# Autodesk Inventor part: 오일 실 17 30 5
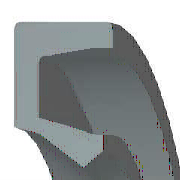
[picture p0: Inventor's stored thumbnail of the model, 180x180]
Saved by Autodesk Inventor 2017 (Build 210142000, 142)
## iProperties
IsCustomPart: 1
Created: 2012-02
Part Number: 오일 실 17 30 5
Material: 고무
Description: 오일 실 - 비스프링, 금속 케이스 GM
Document SubType Name: Modeling
Standard: JIS B 2402
Designer: mduedu
Standards Organization: JIS
Language: ko-KR
Size Designation: 17 30 5 C
Categories: <MemberInstance><Categories><Category DisplayName="샤프트 부품" InternalName="7f7aeb1f-a693-4053-b835-cee3144e0d98" Mnemonic="SHFT"><Category DisplayName="실링" Intern
Density: 0.93 g/cm^3
Appearance: 검은색
Mass: 0.920963 g
Surface Area: 18.5193 cm^2
Volume: 0.990282 cm^3
Author: mduedu
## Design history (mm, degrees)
fillet "모깎기2" dims "d36" = 0.5
body "Solid1"
revolve "회전1" stored, may be unused: angle "d27" = 360 deg
fillet "모깎기1" dims "d28" = 0.25 (= 0.05 x b)
chamfer "모따기1" distance "d29" = 0.07143 (= 0.0142857 x b); stored, may be unused: second distance "d30" = 0.25 (= 0.05 x b), angle "d35" = 45 deg
sketch "스케치2"
  geometry: L1 (-9.367, -3.238)-(-10.233, -3.863); L2 (-8.5, -1.625)-(-9.367, -3.238); L3 (-9.15, -1)-(-8.5, -1.625); L4 (-11.317, -3.75)-(-9.15, -1); L5 (-13.075, -3.75)-(-11.317, -3.75); L6 (-14.375, -1.25)-(-13.075, -3.75); L7 (-14.375, 0)-(-14.375, -1.25); L8 (-15, 0)-(-14.375, 0); L9 (-15, -5)-(-15, 0); L10 (-11.129, -5)-(-15, -5); L11 (-10.233, -3.863)-(-11.129, -5); L12 (0, -9.6)-(0, 1.6) reference; L13 (-14, 0)-(-28, 0) reference
  constraints: 22 end point, 3 horizontal, 2 vertical, 1 parallel
  dimensions: "d2" = 5 distance of L9.start L8.start (= b); "d4" = 1 vertical distance of L8.start L3.start (= 0.2 x b); "d6" = 0.625 distance of L8.start L7.start (= 0.125 x b); "d8" = 1.25 distance of L7.start L6.start (= 0.25 x b); "d10" = 1.25 vertical distance of L5.start L9.start (= 0.25 x b); "d12" = 1.3 horizontal distance of L6.start L5.start (= 0.1 x dd - 0.1 x Diam); "d14" = 1.6129 vertical distance of L2.start L1.start (= 0.322581 x b); "d16" = 0.86667 horizontal distance of L1.start L1.end (= 0.0666667 x dd - 0.0666667 x Diam); "d18" = 0.86667 horizontal distance of L2.start L1.start (= 0.0666667 x dd - 0.0666667 x Diam); "d20" = 0.625 vertical distance of L3.start L2.start (= 0.125 x b); "d22" = 0.65 horizontal distance of L3.start L2.start (= 0.05 x dd - 0.05 x Diam); "d24" = 0.625 vertical distance of L1.start L1.end (= 0.125 x b); "d26" = 2.16667 horizontal distance of L4.start L3.start (= 0.166667 x dd - 0.166667 x Diam); "d31" = 0 distance between parallel lines of L8 L13; "d32" = 15 distance between parallel lines of L12 L9 (= 0.5 x dd); "d33" = 8.5 distance from line of L12 L2.start (= 0.5 x Diam)
other parameters: "Diam" = 17 [user parameter; used in 6 equation terms], "b" = 5 [user parameter; used in 11 equation terms], "d1" = 8 (derived), "d3" = 1.6 (derived), "d5" = 1 (derived), "d7" = 2 (derived), "d9" = 2 (derived), "d11" = 2 (derived), "d13" = 2.58065 (derived), "d15" = 1.33333 (derived), "d17" = 1.33333 (derived), "d19" = 1 (derived), "d21" = 1 (derived), "d23" = 1 (derived), "d25" = 3.33333 (derived), "d34" = 0
